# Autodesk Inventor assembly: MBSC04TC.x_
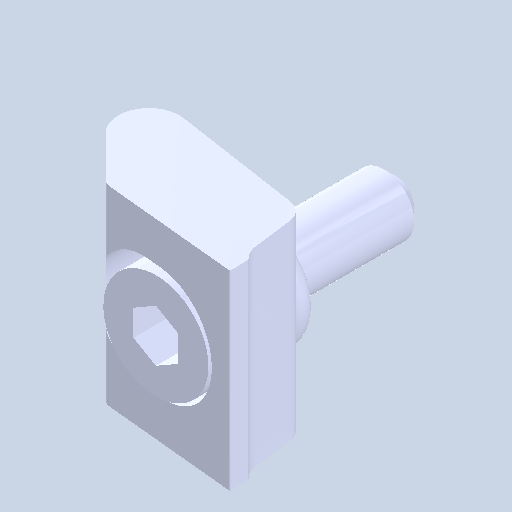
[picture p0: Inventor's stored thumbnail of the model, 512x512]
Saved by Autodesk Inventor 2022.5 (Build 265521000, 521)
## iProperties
Created: 2024-05
Part Number: MBSC04TC.x_
Document SubType Name: Assembly
Designer: ImaoCorp
Author: ImaoCorp
Sending System: SOLIDWORKS 2022-2022290
MC: AMD64
MC_MODEL: Intel64 Family 6 Model 60 Stepping 3, GenuineIntel
OS: Windows_NT
FRU: Parasolid Version 33.1, build 260,  4-25-2022
FORMAT: text
GUISE: transmit
KEY: FILEMBSC04TC.x_t
DATE: Mon May 20 16:28:00 2024
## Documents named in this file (4)
- X:\14_SW2022-Inv2022\保留中\mitee-bite\データ\mbsc04tc\MBSC04TC.x_.iam
- X:\14_SW2022-Inv2022\保留中\mitee-bite\データ\mbsc04tc\MBSC04TC_01.ipt
- X:\14_SW2022-Inv2022\保留中\mitee-bite\データ\mbsc04tc\MBSC04TC_02.ipt
- X:\14_SW2022-Inv2022\保留中\mitee-bite\データ\mbsc04tc\MBSC04TC_03.ipt
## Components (3 placed, 3 different names)
1. MBSC04TC_01
2. MBSC04TC_02
3. MBSC04TC_03
